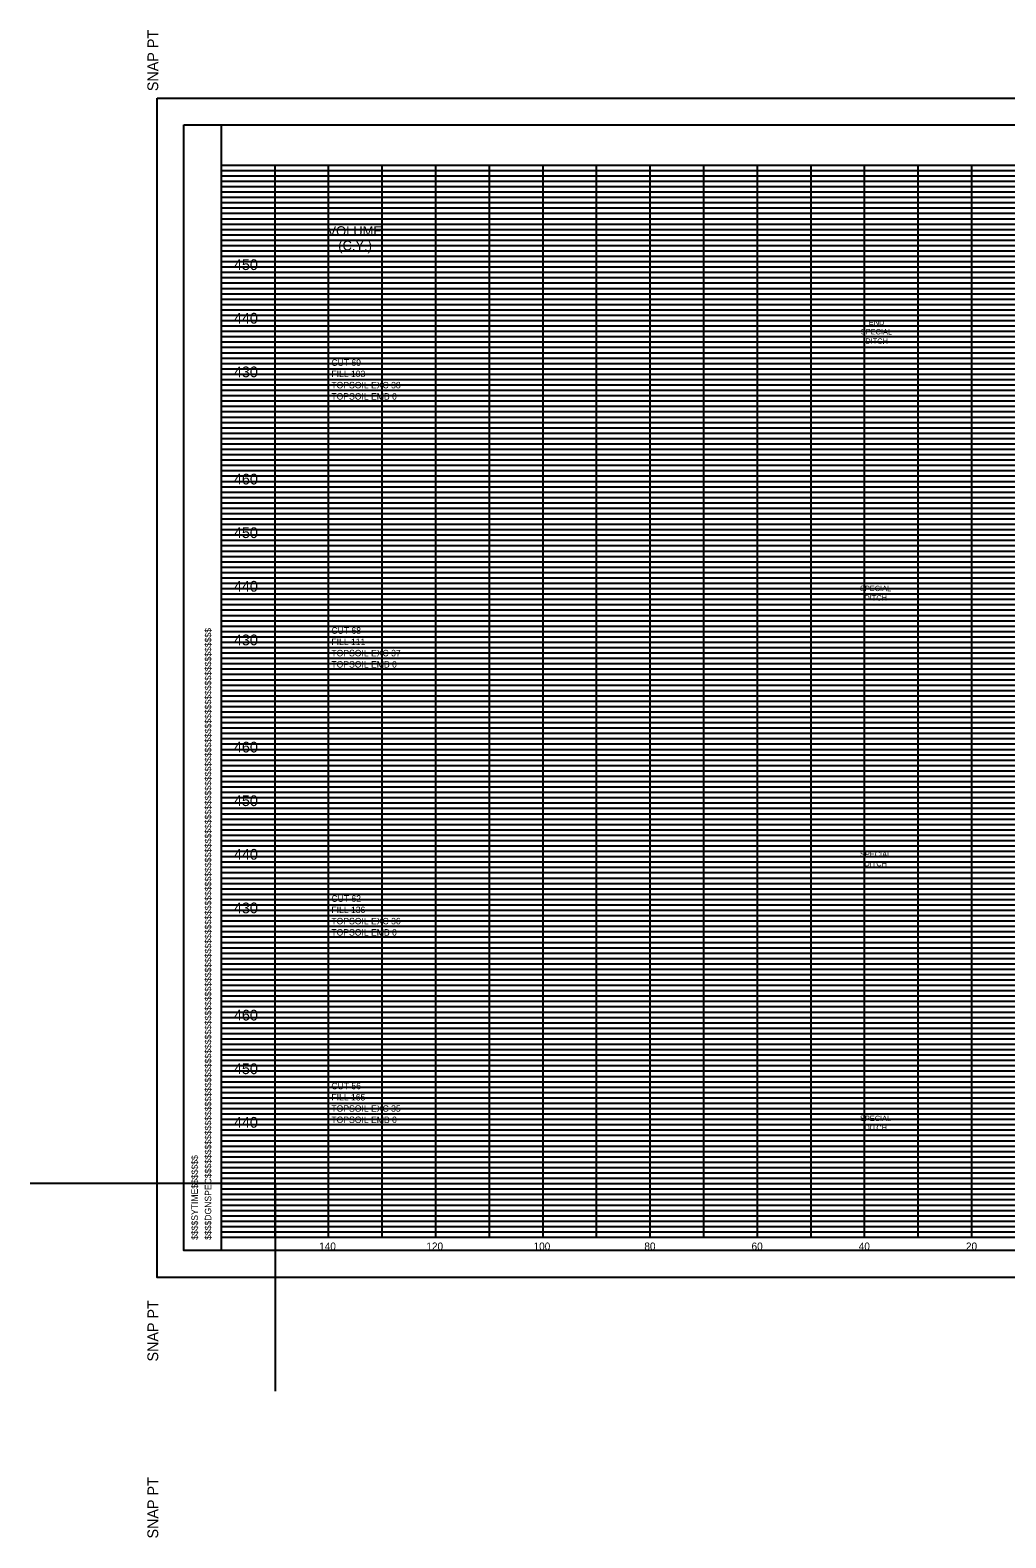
# Model space of a CAD drawing. Extents: x 37 to 1710, y 707 to 2305.
# Drawn here: x 964.3 to 1146.3, y 2023.9 to 2305.2 of the extents above; entities that cross this region are included whole.
import ezdxf

# ---------------------------------------------------------------- set-up
doc = ezdxf.new("R2010")
doc.units = 0
for name, color, linetype in [('DESIGN - DRAINAGE - Special Ditch Width Text', 7, 'Continuous'), ('DESIGN - SCRATCH - User 1', 7, 'Continuous'), ('DESIGN - SHEET - Corner Text', 7, 'Continuous'), ('DESIGN - SHEET - Light Grid', 7, 'Continuous'), ('DESIGN - SHEET - Linework', 7, 'Continuous'), ('DESIGN - SHEET - Plot Shape', 7, 'Continuous'), ('DESIGN - TYPICAL - Text', 7, 'Continuous')]:
    doc.layers.add(name, color=color, linetype=linetype)

msp = doc.modelspace()

# ---------------------------------------------------------------- linework, layer by layer
at = {"layer": 'DESIGN - SCRATCH - User 1'}
for p, q in [((1010, 2090), (964.31, 2090)), ((1010, 2090), (1010, 2051.3)), ((1000, 2080), (1000, 2080))]:
    msp.add_line(p, q, dxfattribs=at)
at = {"layer": 'DESIGN - SHEET - Light Grid'}
for p, q in [((1000, 2279), (1280, 2279)), ((1000, 2278), (1280, 2278)), ((1000, 2277), (1280, 2277)), ((1000, 2276), (1280, 2276)), ((1000, 2275), (1280, 2275)), ((1000, 2274), (1280, 2274)), ((1000, 2273), (1280, 2273)), ((1000, 2272), (1280, 2272)), ((1000, 2271), (1280, 2271)), ((1000, 2269), (1320, 2269)), ((1000, 2268), (1320, 2268)), ((1000, 2267), (1320, 2267)), ((1000, 2266), (1320, 2266)), ((1000, 2265), (1320, 2265)), ((1000, 2264), (1320, 2264)), ((1000, 2263), (1320, 2263)), ((1000, 2262), (1320, 2262)), ((1000, 2261), (1320, 2261)), ((1000, 2259), (1320, 2259)), ((1000, 2258), (1320, 2258)), ((1000, 2257), (1320, 2257)), ((1000, 2256), (1320, 2256)), ((1000, 2255), (1320, 2255)), ((1000, 2254), (1320, 2254)), ((1000, 2253), (1320, 2253)), ((1000, 2252), (1320, 2252)), ((1000, 2251), (1320, 2251)), ((1000, 2249), (1320, 2249)), ((1000, 2248), (1320, 2248)), ((1000, 2247), (1320, 2247)), ((1000, 2246), (1320, 2246)), ((1000, 2245), (1320, 2245)), ((1000, 2244), (1320, 2244)), ((1000, 2243), (1320, 2243)), ((1000, 2242), (1320, 2242)), ((1000, 2241), (1320, 2241)), ((1000, 2239), (1320, 2239)), ((1000, 2238), (1320, 2238)), ((1000, 2237), (1320, 2237)), ((1000, 2236), (1320, 2236)), ((1000, 2235), (1320, 2235)), ((1000, 2234), (1320, 2234)), ((1000, 2233), (1320, 2233)), ((1000, 2232), (1320, 2232)), ((1000, 2231), (1320, 2231)), ((1000, 2229), (1320, 2229)), ((1000, 2228), (1320, 2228)), ((1000, 2227), (1320, 2227)), ((1000, 2226), (1320, 2226)), ((1000, 2225), (1320, 2225)), ((1000, 2224), (1320, 2224)), ((1000, 2223), (1320, 2223)), ((1000, 2222), (1320, 2222)), ((1000, 2221), (1320, 2221)), ((1000, 2219), (1320, 2219)), ((1000, 2218), (1320, 2218)), ((1000, 2217), (1320, 2217)), ((1000, 2216), (1320, 2216)), ((1000, 2215), (1320, 2215)), ((1000, 2214), (1320, 2214)), ((1000, 2213), (1320, 2213)), ((1000, 2212), (1320, 2212)), ((1000, 2211), (1320, 2211)), ((1000, 2209), (1320, 2209)), ((1000, 2208), (1320, 2208)), ((1000, 2207), (1320, 2207)), ((1000, 2206), (1320, 2206)), ((1000, 2205), (1320, 2205)), ((1000, 2204), (1320, 2204)), ((1000, 2203), (1320, 2203)), ((1000, 2202), (1320, 2202)), ((1000, 2201), (1320, 2201)), ((1000, 2199), (1320, 2199)), ((1000, 2198), (1320, 2198)), ((1000, 2197), (1320, 2197)), ((1000, 2196), (1320, 2196)), ((1000, 2195), (1320, 2195)), ((1000, 2194), (1320, 2194)), ((1000, 2193), (1320, 2193)), ((1000, 2192), (1320, 2192)), ((1000, 2191), (1320, 2191)), ((1000, 2189), (1320, 2189)), ((1000, 2188), (1320, 2188)), ((1000, 2187), (1320, 2187)), ((1000, 2186), (1320, 2186)), ((1000, 2185), (1320, 2185)), ((1000, 2184), (1320, 2184)), ((1000, 2183), (1320, 2183)), ((1000, 2182), (1320, 2182)), ((1000, 2181), (1320, 2181)), ((1000, 2179), (1320, 2179)), ((1000, 2178), (1320, 2178)), ((1000, 2177), (1320, 2177)), ((1000, 2176), (1320, 2176)), ((1000, 2175), (1320, 2175)), ((1000, 2174), (1320, 2174)), ((1000, 2173), (1320, 2173)), ((1000, 2172), (1320, 2172)), ((1000, 2171), (1320, 2171)), ((1000, 2169), (1320, 2169)), ((1000, 2168), (1320, 2168)), ((1000, 2167), (1320, 2167)), ((1000, 2166), (1320, 2166)), ((1000, 2165), (1320, 2165)), ((1000, 2164), (1320, 2164)), ((1000, 2163), (1320, 2163)), ((1000, 2162), (1320, 2162)), ((1000, 2161), (1320, 2161)), ((1000, 2159), (1320, 2159)), ((1000, 2158), (1320, 2158)), ((1000, 2157), (1320, 2157)), ((1000, 2156), (1320, 2156)), ((1000, 2155), (1320, 2155)), ((1000, 2154), (1320, 2154)), ((1000, 2153), (1320, 2153)), ((1000, 2152), (1320, 2152)), ((1000, 2151), (1320, 2151)), ((1000, 2149), (1320, 2149)), ((1000, 2148), (1320, 2148)), ((1000, 2147), (1320, 2147)), ((1000, 2146), (1320, 2146)), ((1000, 2145), (1320, 2145)), ((1000, 2144), (1320, 2144)), ((1000, 2143), (1320, 2143)), ((1000, 2142), (1320, 2142)), ((1000, 2141), (1320, 2141)), ((1000, 2139), (1320, 2139)), ((1000, 2138), (1320, 2138)), ((1000, 2137), (1320, 2137)), ((1000, 2136), (1320, 2136)), ((1000, 2135), (1320, 2135)), ((1000, 2134), (1320, 2134)), ((1000, 2133), (1320, 2133)), ((1000, 2132), (1320, 2132)), ((1000, 2131), (1320, 2131)), ((1000, 2129), (1320, 2129)), ((1000, 2128), (1320, 2128)), ((1000, 2127), (1320, 2127)), ((1000, 2126), (1320, 2126)), ((1000, 2125), (1320, 2125)), ((1000, 2124), (1320, 2124)), ((1000, 2123), (1320, 2123)), ((1000, 2122), (1320, 2122)), ((1000, 2121), (1320, 2121)), ((1000, 2119), (1320, 2119)), ((1000, 2118), (1320, 2118)), ((1000, 2117), (1320, 2117)), ((1000, 2116), (1320, 2116)), ((1000, 2115), (1320, 2115)), ((1000, 2114), (1320, 2114)), ((1000, 2113), (1320, 2113)), ((1000, 2112), (1320, 2112)), ((1000, 2111), (1320, 2111)), ((1000, 2109), (1320, 2109)), ((1000, 2108), (1320, 2108)), ((1000, 2107), (1320, 2107)), ((1000, 2106), (1320, 2106)), ((1000, 2105), (1320, 2105)), ((1000, 2104), (1320, 2104)), ((1000, 2103), (1320, 2103)), ((1000, 2102), (1320, 2102)), ((1000, 2101), (1320, 2101)), ((1000, 2099), (1320, 2099)), ((1000, 2098), (1320, 2098)), ((1000, 2097), (1320, 2097)), ((1000, 2096), (1320, 2096)), ((1000, 2095), (1320, 2095)), ((1000, 2094), (1320, 2094)), ((1000, 2093), (1320, 2093)), ((1000, 2092), (1320, 2092)), ((1000, 2091), (1320, 2091)), ((1000, 2089), (1320, 2089)), ((1000, 2088), (1320, 2088)), ((1000, 2087), (1320, 2087)), ((1000, 2086), (1320, 2086)), ((1000, 2085), (1320, 2085)), ((1000, 2084), (1320, 2084)), ((1000, 2083), (1320, 2083)), ((1000, 2082), (1320, 2082)), ((1000, 2081), (1320, 2081))]:
    msp.add_line(p, q, dxfattribs=at)
at = {"layer": 'DESIGN - SHEET - Linework'}
for p, q in [((1000, 2280), (1320, 2280)), ((1010, 2080), (1010, 2280)), ((1020, 2080), (1020, 2280)), ((1030, 2080), (1030, 2280)), ((1040, 2080), (1040, 2280)), ((1050, 2080), (1050, 2280)), ((1060, 2080), (1060, 2280)), ((1070, 2080), (1070, 2280)), ((1080, 2080), (1080, 2280)), ((1090, 2080), (1090, 2280)), ((1100, 2080), (1100, 2280)), ((1110, 2080), (1110, 2280)), ((1120, 2080), (1120, 2280)), ((1130, 2080), (1130, 2280)), ((1140, 2080), (1140, 2280)), ((1000, 2270), (1280, 2270)), ((1000, 2260), (1320, 2260)), ((1000, 2250), (1320, 2250)), ((1000, 2240), (1320, 2240)), ((1000, 2230), (1320, 2230)), ((1000, 2220), (1320, 2220)), ((1000, 2210), (1320, 2210)), ((1000, 2200), (1320, 2200)), ((1000, 2190), (1320, 2190)), ((1000, 2180), (1320, 2180)), ((1000, 2170), (1320, 2170)), ((1000, 2160), (1320, 2160)), ((1000, 2150), (1320, 2150)), ((1000, 2140), (1320, 2140)), ((1000, 2130), (1320, 2130)), ((1000, 2120), (1320, 2120)), ((1000, 2110), (1320, 2110)), ((1000, 2100), (1320, 2100)), ((1000, 2090), (1320, 2090)), ((1000, 2080), (1320, 2080))]:
    msp.add_line(p, q, dxfattribs=at)
for points in [[(988, 2292.5), (1328, 2292.5), (1328, 2072.5), (988, 2072.5)], [(1000, 2287.5), (1320, 2287.5), (1320, 2077.5), (1000, 2077.5)]]:
    msp.add_lwpolyline(points, close=True, dxfattribs=at)
at = {"layer": 'DESIGN - SHEET - Plot Shape'}
msp.add_lwpolyline([(993, 2287.5), (1323, 2287.5), (1323, 2077.5), (993, 2077.5)], close=True, dxfattribs=at)

# ---------------------------------------------------------------- texts
at = {"layer": 'DESIGN - DRAINAGE - Special Ditch Width Text'}
for s, p in [('END', (1120.78, 2250.16)), ('SPECIAL ', (1119.28, 2248.42)), ('DITCH', (1120.12, 2246.67)), ('SPECIAL ', (1119.12, 2200.54)), ('DITCH', (1119.96, 2198.78)), ('SPECIAL ', (1119.12, 2150.96)), ('DITCH', (1119.96, 2149.2)), ('SPECIAL ', (1119.12, 2101.68)), ('DITCH', (1119.96, 2099.92))]:
    msp.add_text(s, height=1, rotation=359.6675, dxfattribs=at).set_placement(p)
at = {"layer": 'DESIGN - SHEET - Corner Text'}
for s, height, p in [('  SNAP PT', 2, (988.2, 2292.3)), ('$$$$DGNSPEC$$$$$$$$$$$$$$$$$$$$$$$$$$$$$$$$$$$$$$$$$$$$$$$$$$$$$$$$$$$$$$$$$$$$$$$$$$$$$$$$$$$$$$$$$$$$$$$$$$$$$$$$$$$$$$$$$$$', 1.2, (998.1, 2079.5)), ('$$$$SYTIME$$$$$$$', 1.2, (995.6, 2079.5)), ('SNAP PT  ', 2, (988.2, 2056.8)), ('  SNAP PT', 2, (988.2, 2022.3))]:
    msp.add_text(s, height=height, rotation=90, dxfattribs=at).set_placement(p)
at = {"layer": 'DESIGN - TYPICAL - Text'}
for s, height, p in [('VOLUME', 1.8, (1019.79, 2266.79)), ('   (C.Y.)', 1.8, (1019.79, 2264.09)), ('     450     ', 2, (998.62, 2260.42)), ('     440     ', 2, (998.62, 2250.42)), ('     430     ', 2, (998.62, 2240.42)), ('CUT 69', 1.2, (1020.51, 2242.55)), ('FILL 103', 1.2, (1020.51, 2240.45)), ('TOPSOIL EXC 38 ', 1.2, (1020.51, 2238.35)), ('TOPSOIL EMB 0', 1.2, (1020.51, 2236.25)), ('     460     ', 2, (998.62, 2220.42)), ('     450     ', 2, (998.62, 2210.42)), ('     440     ', 2, (998.62, 2200.42)), ('     430     ', 2, (998.62, 2190.42)), ('CUT 68', 1.2, (1020.51, 2192.56)), ('FILL 111', 1.2, (1020.51, 2190.46)), ('TOPSOIL EXC 37', 1.2, (1020.51, 2188.36)), ('TOPSOIL EMB 0', 1.2, (1020.51, 2186.26)), ('     460     ', 2, (998.62, 2170.42)), ('     450     ', 2, (998.62, 2160.42)), ('     440     ', 2, (998.62, 2150.42)), ('CUT 62', 1.2, (1020.51, 2142.56)), ('     430     ', 2, (998.62, 2140.42)), ('FILL 136', 1.2, (1020.51, 2140.46)), ('TOPSOIL EXC 36', 1.2, (1020.51, 2138.36)), ('TOPSOIL EMB 0', 1.2, (1020.51, 2136.26)), ('     460     ', 2, (998.62, 2120.42)), ('     450     ', 2, (998.62, 2110.42)), ('CUT 56', 1.2, (1020.51, 2107.6)), ('FILL 165', 1.2, (1020.51, 2105.5)), ('TOPSOIL EXC 35', 1.2, (1020.51, 2103.4)), ('     440     ', 2, (998.62, 2100.42)), ('TOPSOIL EMB 0', 1.2, (1020.51, 2101.3)), ('     140     ', 1.4, (1015.63, 2077.6)), ('     120     ', 1.4, (1035.63, 2077.6)), ('     100     ', 1.4, (1055.63, 2077.6)), ('     80     ', 1.4, (1076.3, 2077.6)), ('     60     ', 1.4, (1096.3, 2077.6)), ('     40     ', 1.4, (1116.3, 2077.6)), ('     20     ', 1.4, (1136.3, 2077.6))]:
    msp.add_text(s, height=height, dxfattribs=at).set_placement(p)

doc.saveas('drawing.dxf')
